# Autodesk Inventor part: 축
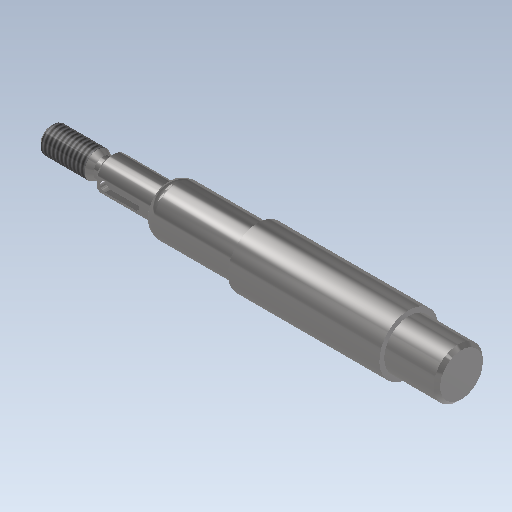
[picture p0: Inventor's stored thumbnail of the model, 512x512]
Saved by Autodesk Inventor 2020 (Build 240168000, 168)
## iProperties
Created: 2015-11
Part Number: 축
Material: 강철, 연강
Document SubType Name: Modeling
Designer: mduedu
Density: 1 g/cm^3
Appearance: 반광택
Author: mduedu
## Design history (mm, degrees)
sketch "스케치1"
  geometry: L1 (-86, 0)-(86, 0); L2 (-86, 0)-(-86, 4); L3 (-86, 4)-(-71.732, 4); L4 (-71.732, 4)-(-70, 3); L5 (-70, 3)-(-68, 3); L6 (-68, 3)-(-68, 5); L7 (-68, 5)-(-50, 5); L8 (-50, 5)-(-50, 6.55); L9 (-48.355, 7.5)-(-23, 7.5); L10 (-23, 7.5)-(-23, 9); L11 (0, 0)-(0, 9); L12 (86, 4)-(71.732, 4); L13 (71.732, 4)-(70, 3); L14 (70, 3)-(68, 3); L15 (68, 3)-(68, 5); L16 (68, 5)-(50, 5); L17 (23, 7.5)-(23, 9); L18 (86, 0)-(86, 4); L19 (-23, 9)-(23, 9); L20 (-50, 6.55)-(-48.355, 7.5); L21 (48.355, 7.5)-(23, 7.5); L22 (50, 6.55)-(48.355, 7.5); L23 (50, 5)-(50, 6.55); 1 further point
  constraints: 46 end point, 10 symmetric about line, 6 perpendicular, 5 parallel, 2 midpoint, 1 coincident, 1 horizontal
  dimensions: "d0" = 172 distance of L1.start L1.end (derived); "d1" = 8 diameter of L3 L1; "d2" = 30 deg angle of L4 L5; "d3" = 6 diameter of L5 L1; "d4" = 10 diameter of L7 L1; "d5" = 15 diameter of L9 L1; "d6" = 18 diameter of L19 L1; "d8" = 18 distance of L6.end L7.end; "d9" = 46 distance of L10.end L17.end; "d10" = 2 distance of L4.end L5.end; "d11" = 16 distance from line of L4.end L2; "d16" = 13.1 diameter of L8.end L1; "d17" = 30 deg angle of L20 L9; "d18" = 27 distance between parallel lines of L10 L8
revolve "회전1" sketch "스케치1" stored, may be unused: angle "d12" = 90 deg
chamfer "모따기1" distance "d13" = 1; stored, may be unused: second distance "d14" = 2, angle "d15" = 45 deg
fillet "모깎기1" dims "d19" = 4, "d20" = 0.5
node "작업 평면1"
sketch "스케치2" dims "d23" = 12
  geometry: L1 (-5.5, 1.5)-(3.5, 1.5); L2 (3.5, 1.5)-(3.5, -1.5); L3 (3.5, -1.5)-(-5.5, -1.5); L4 (-5.5, -1.5)-(-5.5, 1.5); L5 (-9, -4)-(-9, 4) reference; 3 further points
  constraints: 8 end point, 2 midpoint, 2 parallel, 2 vertical alignment, 1 horizontal, 1 perpendicular, 4 other
  dimensions: "d21" = 3 distance between parallel lines of L3 L1; "d24" = 2 dimension on L5
extrude "돌출1" cut sketch "스케치2" distance "d25" = 1.8; taper "d26" = 0 deg
feature "스레드1" dims "d27" = 10, "d28" = 0
feature "스레드2" dims "d29" = 10, "d30" = 0
chamfer "모따기2" distance "d31" = 1; stored, may be unused: second distance "d32" = 2, angle "d33" = 45 deg
node "작업 평면2"
sketch "스케치3"
  geometry: C1 r 7.5 at (0, 0) reference; 1 further point
extrude "돌출2" cut sketch "스케치3" extent not by distance; stored distance "d36" = 10; taper "d37" = 0 deg
chamfer "모따기3" distance "d38" = 1; stored, may be unused: second distance "d39" = 2, angle "d40" = 45 deg
node "솔리드1"
mirror "대칭1"
node "절단 모서리 투영1"
other parameters: "d35" = 16
